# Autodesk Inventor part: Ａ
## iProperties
Created: 2007-08
Part Number: Ａ
Document SubType Name: Modeling
Designer: t-ikumi
Author: t-ikumi
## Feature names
1. 押し出し1 [Extrusion]
2. 押し出し2 [Extrusion]
3. 面取り1 [Chamfer]
4. シェル1
5. 押し出し3 [Extrusion]
6. ミラー1 [Mirror]
7. 押し出し4 [Extrusion]
8. 押し出し5 [Extrusion]
9. 押し出し6 [Extrusion]
10. 放射状パターン1 [Circular Pattern]
11. 面取り2 [Chamfer]
12. 面取り3 [Chamfer]
13. 面取り4 [Chamfer]
14. 面取り5 [Chamfer]
15. 面取り6 [Chamfer]
